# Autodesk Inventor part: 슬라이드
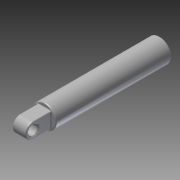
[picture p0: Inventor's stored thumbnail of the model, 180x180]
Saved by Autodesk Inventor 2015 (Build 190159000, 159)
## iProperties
Created: 2016-02
Part Number: 슬라이드
Material: 강철, 연강
Document SubType Name: Modeling
Designer: test
Density: 1 g/cm^3
Appearance: 강철
Author: test
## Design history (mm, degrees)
sketch "스케치2"
  geometry: C1 r 6 at (0, 0); 1 further point
  constraints: 1 centre point, 1 coincident
  dimensions: "d0" = 12 diameter of C1
extrude "돌출1" new body sketch "스케치2" distance "d1" = 60; taper "d2" = 0 deg
hole "구멍1" diameter "d5" = 5.917; stored, may be unused: countersink angle "d9" = 90 deg, drill point angle "d11" = 118 deg; dims "d3" = 10, "d4" = 10, "d6" = 10, "d7" = 4, "d8" = 2, "d10" = 12
chamfer "모따기1" distance "d12" = 1; stored, may be unused: second distance "d13" = 2, angle "d14" = 45 deg
sketch "스케치3"
  geometry: L1 (0, 6)-(0, -6) reference; L2 (0, 4)-(-9, 4); L3 (-9, -4)-(0, -4); L4 (0, -4)-(0, 4); C1 r 2.5 at (-9, 0); A1 r 4 centre (-9, 0) between (-9, 4) and (-9, -4); 2 further points
  constraints: 6 end point, 2 centre point, 2 point on circle, 2 tangent, 1 coincident, 1 horizontal, 1 horizontal alignment, 1 midpoint, 1 parallel, 1 point on line, 1 vertical
  dimensions: "d15" = 13 dimension on A1 L1; "d16" = 8 distance between parallel lines of L3 L2; "d17" = 5 diameter of C1
extrude "돌출2" join sketch "스케치3" stored distance "d18" = 7; taper "d19" = 0 deg
chamfer "모따기2" distance "d20" = 0.5; stored, may be unused: second distance "d21" = 2, angle "d22" = 45 deg
fillet "모깎기1" dims "d23" = 0.5
fillet "모깎기2" dims "d24" = 0.5
fillet "모깎기3" dims "d25" = 0.5
sketch "스케치4"
  geometry: 1 further point
node "솔리드1"
